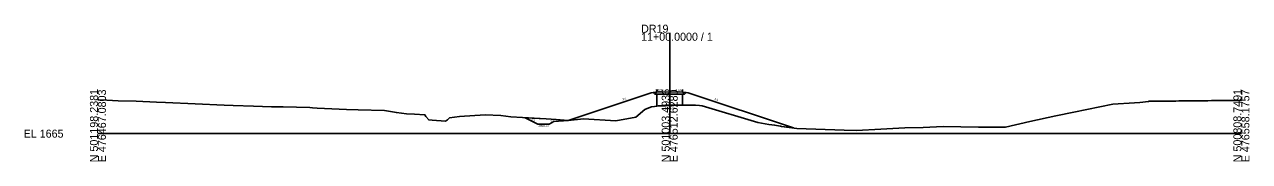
# Model space of a CAD drawing. Extents: x 79370 to 79799, y -95930 to -94349.
# Drawn here: x 79370.3 to 79798.8, y -94930.2 to -94882.5 of the extents above; entities that cross this region are included whole.
import ezdxf

# ---------------------------------------------------------------- set-up
doc = ezdxf.new("R2010")
doc.units = 0
for name, color, linetype in [('Exist Cross Section Cell', 7, 'Continuous'), ('Exist XS Center Line Elevation Label', 7, 'Continuous'), ('Exist XS Ground Line', 7, 'Continuous'), ('Prop XS DDE', 7, 'Continuous'), ('Prop XS DDE Earthwork Shape', 7, 'Continuous'), ('Prop XS Ditch Standard Text', 7, 'Continuous'), ('Prop XS Earthwork Shape', 7, 'Continuous'), ('Prop XS EOT Tick Mark', 7, 'Continuous'), ('Prop XS Finish Grade', 7, 'Continuous'), ('Prop XS Finish Grade Earthwork', 7, 'Continuous'), ('Prop XS Finish Grade Pavement', 7, 'Continuous'), ('Prop XS Pvmt Edge Slope', 7, 'Continuous'), ('Prop XS SE Text', 7, 'Continuous'), ('Prop XS Shoulder Borrow Shape', 7, 'Continuous'), ('Prop XS Side Slope Text', 7, 'Continuous'), ('Prop XS Subgrade Earthwork', 7, 'Continuous'), ('Scratch_Level_6', 7, 'Continuous')]:
    doc.layers.add(name, color=color, linetype=linetype)

msp = doc.modelspace()

# ---------------------------------------------------------------- linework, layer by layer
at = {"layer": 'Exist Cross Section Cell'}
for p, q in [((79596.01, -94920.51), (79596.01, -94885.31)), ((79396.01, -94920.51), (79596.01, -94920.51)), ((79596.01, -94920.51), (79796.01, -94920.51))]:
    msp.add_line(p, q, dxfattribs=at)
at = {"layer": 'Exist XS Ground Line'}
msp.add_lwpolyline([(79396.01, -94908.77), (79399.12, -94908.88), (79403.08, -94909.11), (79409.39, -94909.22), (79416.49, -94909.51), (79419.67, -94909.62), (79430.07, -94910.1), (79440.21, -94910.59), (79443.3, -94910.71), (79450.48, -94910.97), (79456.71, -94911.12), (79460.75, -94911.17), (79470.12, -94911.44), (79471.09, -94911.47), (79472.73, -94911.58), (79482.91, -94912.12), (79487.05, -94912.18), (79496.21, -94912.43), (79500.43, -94913.15), (79503.91, -94913.57), (79506.7, -94913.75), (79510.39, -94913.97), (79510.73, -94914.51), (79511.72, -94915.71), (79512.91, -94915.77), (79517.57, -94916.18), (79518.33, -94915.64), (79519.01, -94914.94), (79522.43, -94914.58), (79531.52, -94913.93), (79536.98, -94914.22), (79540.48, -94914.59), (79544.52, -94914.9), (79552.75, -94915.37), (79556.29, -94915.57), (79560.54, -94915.89), (79565.82, -94915.4), (79577.22, -94916.01), (79584.16, -94914.81), (79587.33, -94912.14), (79588.76, -94911.53), (79589.69, -94911.17), (79590.68, -94911.06), (79592.02, -94910.76), (79594.55, -94910.63), (79596.01, -94910.57), (79598.87, -94910.6), (79600.37, -94910.59), (79605.09, -94910.58), (79606.42, -94910.65), (79607.42, -94910.79), (79626.85, -94916.61), (79630.74, -94917.27), (79631.75, -94917.39), (79632.74, -94917.5), (79634.76, -94917.9), (79635.09, -94917.96), (79640.55, -94918.67), (79657.1, -94919.29), (79661.33, -94919.37), (79669.84, -94918.92), (79678.24, -94918.45), (79684.64, -94918.39), (79691.64, -94918.04), (79704.04, -94918.21), (79713.47, -94918.28), (79722.02, -94916.33), (79731.14, -94914.31), (79737.38, -94913.05), (79751.09, -94910.24), (79758.59, -94909.81), (79760.45, -94909.6), (79763.46, -94909.25), (79763.79, -94909.21), (79764.16, -94909.21), (79766.26, -94909.2), (79766.57, -94909.2), (79768.24, -94909.18), (79769.19, -94909.17), (79771.44, -94909.15), (79773.1, -94909.13), (79774.07, -94909.12), (79775.25, -94909.11), (79776.54, -94909.09), (79777.23, -94909.09), (79779.45, -94909.06), (79780.24, -94909.06), (79781.68, -94909.04), (79783.56, -94909.02), (79784.27, -94909.02), (79785.56, -94909), (79786.89, -94908.98), (79787.96, -94908.97), (79789.14, -94908.95), (79790.02, -94908.94), (79790.45, -94908.93), (79790.89, -94908.94), (79791.7, -94908.93), (79792.14, -94908.93), (79793.95, -94908.95), (79794.54, -94908.95), (79796.01, -94908.96)], dxfattribs=at)
at = {"layer": 'Prop XS DDE'}
for p, q in [((79545.42, -94914.95), (79549.84, -94917.16)), ((79553.84, -94917.16), (79549.84, -94917.16)), ((79555.53, -94916.31), (79553.84, -94917.16)), ((79555.53, -94916.31), (79560.53, -94915.89))]:
    msp.add_line(p, q, dxfattribs=at)
at = {"layer": 'Prop XS DDE Earthwork Shape'}
msp.add_lwpolyline([(79555.53, -94916.31), (79553.84, -94917.16), (79549.84, -94917.16), (79545.42, -94914.95), (79552.75, -94915.37), (79556.29, -94915.57), (79560.53, -94915.89)], close=True, dxfattribs=at)
at = {"layer": 'Prop XS Earthwork Shape'}
for points in [[(79591.51, -94906.74), (79590.83, -94906.76), (79590.25, -94906.18), (79589.51, -94906.23), (79560.53, -94915.89), (79565.82, -94915.4), (79577.22, -94916.01), (79584.16, -94914.81), (79587.33, -94912.14), (79588.76, -94911.53), (79589.69, -94911.17), (79590.68, -94911.06), (79591.51, -94910.87)], [(79600.49, -94906.74), (79591.51, -94906.74), (79590.83, -94906.76), (79590.25, -94906.18), (79589.51, -94906.23), (79560.53, -94915.89), (79565.82, -94915.4), (79577.22, -94916.01), (79584.16, -94914.81), (79587.33, -94912.14), (79588.76, -94911.53), (79589.69, -94911.17), (79590.68, -94911.06), (79592.02, -94910.76), (79594.55, -94910.63), (79596.01, -94910.57), (79598.87, -94910.6), (79600.37, -94910.59), (79605.09, -94910.58), (79606.42, -94910.65), (79607.42, -94910.79), (79626.85, -94916.61), (79630.74, -94917.27), (79631.75, -94917.39), (79632.74, -94917.5), (79634.76, -94917.9), (79635.09, -94917.96), (79639.35, -94918.52), (79602.51, -94906.23), (79601.77, -94906.18), (79601.19, -94906.76)], [(79600.49, -94906.74), (79601.19, -94906.76), (79601.77, -94906.18), (79602.51, -94906.23), (79639.35, -94918.52), (79635.09, -94917.96), (79634.76, -94917.9), (79632.74, -94917.5), (79631.75, -94917.39), (79630.74, -94917.27), (79626.85, -94916.61), (79607.42, -94910.79), (79606.42, -94910.65), (79605.09, -94910.58), (79600.49, -94910.59)]]:
    msp.add_lwpolyline(points, close=True, dxfattribs=at)
at = {"layer": 'Prop XS EOT Tick Mark'}
for p, q in [((79591.51, -94906.07), (79591.51, -94905.07)), ((79600.51, -94906.07), (79600.51, -94905.07))]:
    msp.add_line(p, q, dxfattribs=at)
at = {"layer": 'Prop XS Finish Grade'}
for p, q in [((79591.51, -94906.07), (79590.25, -94906.18)), ((79600.51, -94906.07), (79601.77, -94906.18))]:
    msp.add_line(p, q, dxfattribs=at)
at = {"layer": 'Prop XS Finish Grade Earthwork'}
for p, q in [((79589.51, -94906.23), (79560.53, -94915.89)), ((79590.25, -94906.18), (79589.51, -94906.23)), ((79601.77, -94906.18), (79602.51, -94906.23)), ((79602.51, -94906.23), (79639.35, -94918.52))]:
    msp.add_line(p, q, dxfattribs=at)
at = {"layer": 'Prop XS Finish Grade Pavement'}
for p, q in [((79591.51, -94906.07), (79596.01, -94905.98)), ((79596.01, -94905.98), (79600.51, -94906.07))]:
    msp.add_line(p, q, dxfattribs=at)
at = {"layer": 'Prop XS Pvmt Edge Slope'}
for p, q in [((79591.51, -94906.07), (79590.83, -94906.76)), ((79600.51, -94906.07), (79601.19, -94906.76))]:
    msp.add_line(p, q, dxfattribs=at)
at = {"layer": 'Prop XS Shoulder Borrow Shape'}
for points in [[(79591.51, -94906.07), (79590.25, -94906.18), (79590.83, -94906.76)], [(79600.51, -94906.07), (79601.77, -94906.18), (79601.19, -94906.76)]]:
    msp.add_lwpolyline(points, close=True, dxfattribs=at)
at = {"layer": 'Prop XS Subgrade Earthwork'}
for p, q in [((79590.83, -94906.76), (79590.25, -94906.18)), ((79591.51, -94906.74), (79590.83, -94906.76)), ((79600.49, -94906.74), (79591.51, -94906.74)), ((79600.49, -94906.74), (79601.19, -94906.76)), ((79601.19, -94906.76), (79601.77, -94906.18))]:
    msp.add_line(p, q, dxfattribs=at)
at = {"layer": 'Scratch_Level_6'}
msp.add_line((79591.51, -94910.87), (79600.49, -94910.59), dxfattribs=at)

# ---------------------------------------------------------------- texts
at = {"layer": 'Exist Cross Section Cell'}
for s, p in [('11+00.0000 / 1', (79586.01, -94888.11)), ('DR19', (79586.01, -94885.31)), ('EL 1665', (79370.01, -94921.91))]:
    msp.add_text(s, height=2.8, dxfattribs=at).set_placement(p)
for s, p in [('N 501198.2381', (79396.01, -94930.51)), ('E 476467.0803', (79398.81, -94930.51)), ('N 501003.4936', (79596.01, -94930.51)), ('E 476512.6280', (79598.81, -94930.51)), ('N 500808.7491', (79796.01, -94930.51)), ('E 476558.1757', (79798.81, -94930.51))]:
    msp.add_text(s, height=2.8, rotation=90, dxfattribs=at).set_placement(p)
at = {"layer": 'Exist XS Center Line Elevation Label'}
msp.add_text('1674.94', height=0.75, dxfattribs=at).set_placement((79594.32, -94912.1))
at = {"layer": 'Prop XS Ditch Standard Text'}
msp.add_text('1668.35', height=0.75, dxfattribs=at).set_placement((79550.04, -94918.07))
at = {"layer": 'Prop XS SE Text'}
for rotation, p in [(1.1458, (79590.91, -94905.75)), (358.8542, (79598.06, -94905.79))]:
    msp.add_text('0.020', height=0.75, rotation=rotation, dxfattribs=at).set_placement(p)
at = {"layer": 'Prop XS Side Slope Text'}
for s, rotation, p in [('3:1', 18.4349, (79579.59, -94909.01)), ('3:1', 341.5651, (79611.55, -94908.72)), ('2:1', 333.5223, (79547.55, -94915.76)), ('2:1', 26.5418, (79554.46, -94916.67))]:
    msp.add_text(s, height=0.75, rotation=rotation, dxfattribs=at).set_placement(p)

doc.saveas('drawing.dxf')
